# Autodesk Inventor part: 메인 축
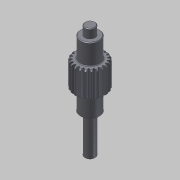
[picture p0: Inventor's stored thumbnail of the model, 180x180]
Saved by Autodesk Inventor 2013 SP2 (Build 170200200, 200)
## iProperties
Created: 2016-02
Part Number: 메인 축
Material: 강철, 연강
Document SubType Name: Modeling
Categories: <?xml version="1.0" encoding="UTF-16"?> <MemberInstance><Categories><FamilyTemplate><FamilyTemplateParameter ValueType="xs:double" Id="1" ObjectReferenceKey="da
Density: 7.86 g/cm^3
CustomPartVersion: 1
Author: mdu
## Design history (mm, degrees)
sketch "Sketch1"
  geometry: C1 r 12 at (0, 0)
  constraints: 1 centre point
  dimensions: "d0" = 24 diameter of C1 (= da_da)
extrude "Extrusion1" new body sketch "Sketch1" distance "d1" = 20 (= da_b); taper "d2" = 0 deg
workplane "Work Plane2"
feature "피치 지름" dims "d4" = 10, "d5" = 0
workplane "Work Plane8"
workplane "Work Plane9"
chamfer "모따기1" distance "d49" = 1; stored, may be unused: second distance "d50" = 2, angle "d51" = 45 deg
sketch "스케치3"
  geometry: C1 r 7.5 at (0, 0); 1 further point
  constraints: 1 centre point, 1 coincident
  dimensions: "d52" = 15 diameter of C1
extrude "돌출2" join sketch "스케치3" distance "d53" = 16; taper "d54" = 0 deg
sketch "스케치4"
  geometry: C1 r 4 at (0, 0); 1 further point
  constraints: 1 centre point, 1 coincident
  dimensions: "d55" = 8 diameter of C1
extrude "돌출3" join sketch "스케치4" distance "d56" = 7; taper "d57" = 0 deg
sketch "스케치5"
  geometry: C1 r 7.5 at (0, 0) reference; C2 r 7.5 at (0, 0) reference; 1 further point
extrude "돌출4" join sketch "스케치5" distance "d62" = 16; taper "d63" = 0 deg
sketch "스케치6"
  geometry: C1 r 4 at (0, 0); 1 further point
  constraints: 1 centre point, 1 coincident
  dimensions: "d64" = 8 diameter of C1
extrude "돌출5" join sketch "스케치6" distance "d65" = 30; taper "d66" = 0 deg
chamfer "모따기2" distance "d58" = 0.5; stored, may be unused: second distance "d59" = 2, angle "d60" = 45 deg
fillet "모깎기1" dims "d61" = 0.5
feature "스퍼 기어" dims "da_b" = 20, "da_d" = 22, "da_aw" = 31, "da_da" = 24, "da_df" = 19.5, "da_dw" = 22, angle "da_beta" = 0 deg, "da_lefttooth" = 0, "da_righttooth" = 0
body "Solid1"
sketch "Sketch2"
  geometry: C1 r 12 at (0, 0) reference; C2 r 11 at (0, 0)
  constraints: 1 centre point, 1 coincident
  dimensions: "d3" = 22 diameter of C2 (= da_dw)
body "Srf1"
node "투영된 루프1"
other parameters: "d16" = 31 (= da_aw), "d17" = 0, "d34" = 1.428 (computed from da_z), "d39" = 0, "d41" = 0, "d43" = 31 (= da_aw), "d46" = 31 (= da_aw), "d47" = 0, "d48" = 0
